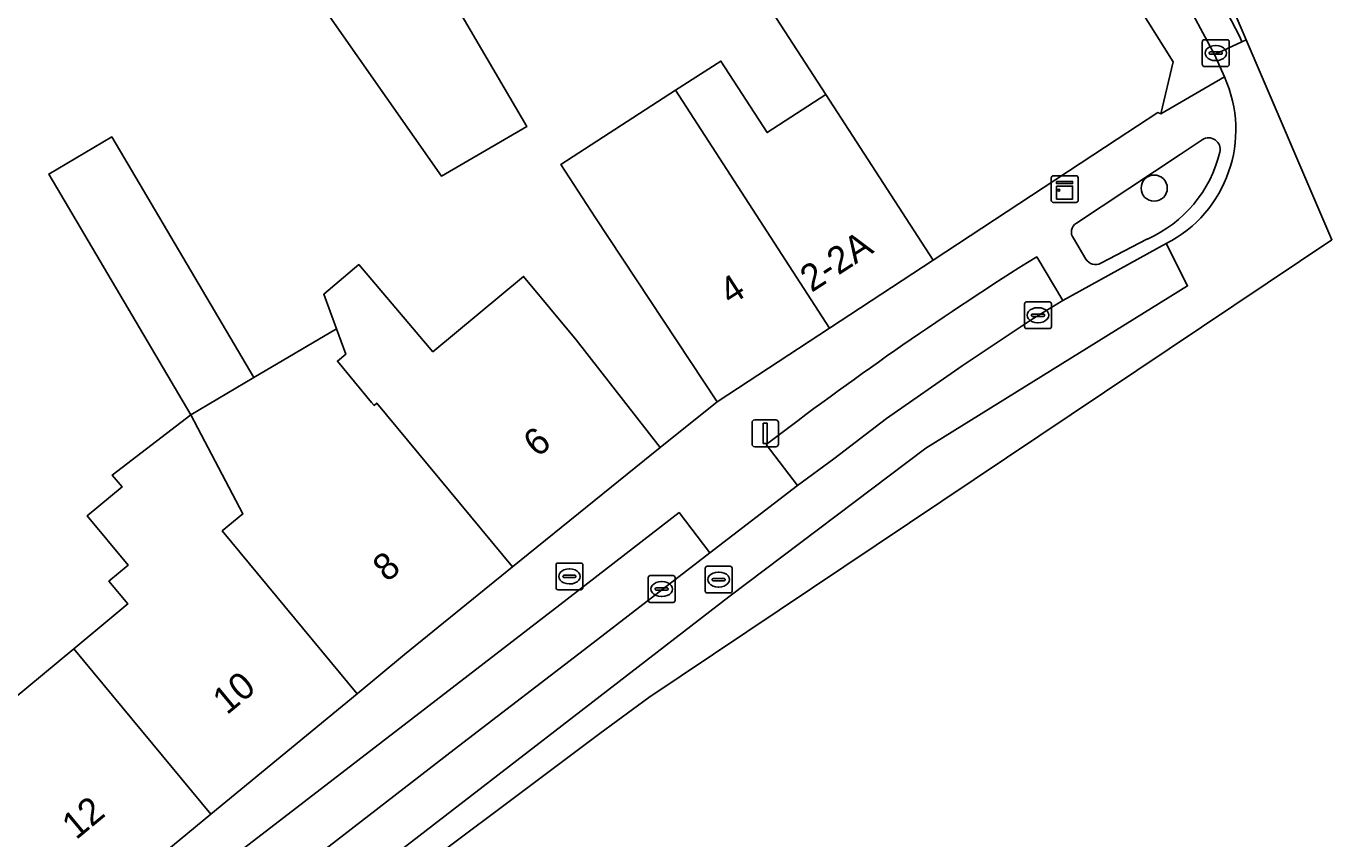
# Model space of a CAD drawing. Extents: x 159371 to 159986, y 382987 to 383597.
# Drawn here: x 159937.11 to 159985.83, y 383267.38 to 383297.7 of the extents above; entities that cross this region are included whole.
import ezdxf

# ---------------------------------------------------------------- set-up
doc = ezdxf.new("R2010")
doc.units = 0
for name, color, linetype in [('IMGEO_Boom', 7, 'Continuous'), ('IMGEO_Brandkraan', 7, 'Continuous'), ('IMGEO_Erf', 7, 'Continuous'), ('IMGEO_Groenvoorziening', 7, 'Continuous'), ('IMGEO_Kast', 7, 'Continuous'), ('IMGEO_Kolk', 7, 'Continuous'), ('IMGEO_Lichtmast', 7, 'Continuous'), ('IMGEO_Pand', 7, 'Continuous'), ('IMGEO_Pand_nummerreeks', 7, 'Continuous'), ('IMGEO_Parkeervlak_open', 7, 'Continuous'), ('IMGEO_Rijbaan_lokaal_gesloten', 7, 'Continuous'), ('IMGEO_Rijbaan_lokaal_open', 7, 'Continuous'), ('IMGEO_Rioolput', 7, 'Continuous'), ('IMGEO_Voetpad_open', 7, 'Continuous')]:
    doc.layers.add(name, color=color, linetype=linetype)

msp = doc.modelspace()

# ---------------------------------------------------------------- linework, layer by layer
at = {"layer": 'IMGEO_Boom'}
msp.add_circle((159979.2, 383291.659), 0.489, dxfattribs=at)
at = {"layer": 'IMGEO_Brandkraan'}
for p, q in [((159956.881, 383276.743), (159956.881, 383277.595)), ((159956.956, 383277.669), (159957.808, 383277.669)), ((159957.882, 383277.595), (159957.882, 383276.743)), ((159957.14, 383277.163), (159957.14, 383277.175)), ((159957.578, 383277.126), (159957.18, 383277.126)), ((159957.183, 383277.212), (159957.581, 383277.212)), ((159957.369, 383277.449), (159957.394, 383277.449)), ((159957.624, 383277.175), (159957.624, 383277.163)), ((159957.808, 383276.669), (159956.956, 383276.669)), ((159957.392, 383276.889), (159957.367, 383276.889))]:
    msp.add_line(p, q, dxfattribs=at)
for points in [[(159956.881, 383276.743), (159956.881, 383277.595)], [(159956.956, 383277.669), (159957.808, 383277.669)], [(159957.882, 383277.595), (159957.882, 383276.743)], [(159957.808, 383276.669), (159956.956, 383276.669)]]:
    msp.add_lwpolyline(points, dxfattribs=at)
for centre, radius, start, end in [((159956.958, 383277.593), 0.0765, 91.552, 178.448), ((159956.958, 383277.593), 0.0765, 91.552, 178.448), ((159957.806, 383277.593), 0.0765, 1.552, 88.448), ((159957.806, 383277.593), 0.0765, 1.552, 88.448), ((159957.18, 383277.172), 0.0403, 85.8775, 175.7526), ((159957.177, 383277.162), 0.0366, 178.938, 274.7102), ((159957.581, 383277.169), 0.043, 264.8664, 352.4533), ((159957.585, 383277.174), 0.0386, 1.7309, 96.639), ((159956.958, 383276.745), 0.0765, 181.552, 268.448), ((159956.958, 383276.745), 0.0765, 181.552, 268.448), ((159957.806, 383276.745), 0.0765, 271.552, 358.448), ((159957.806, 383276.745), 0.0765, 271.552, 358.448)]:
    msp.add_arc(centre, radius, start, end, dxfattribs=at)
for centre, major_axis, ratio, start_param, end_param in [((159957.368, 383277.169), (-0.387, 0.002), 0.722429, 4.712389, 7.853982), ((159957.393, 383277.169), (-0.39, 0.002), 0.717154, 1.570796, 4.712389)]:
    msp.add_ellipse(centre, major_axis=major_axis, ratio=ratio, start_param=start_param, end_param=end_param, dxfattribs=at)
at = {"layer": 'IMGEO_Erf'}
for points in [[(159934.071, 383312.263), (159942.713, 383316.486), (159947.811, 383307.547), (159949.364, 383304.957), (159949.605, 383304.544), (159949.745, 383304.614), (159948.027, 383308.209), (159950.905, 383309.585), (159952.605, 383306.029), (159954.438, 383306.935), (159956.105, 383303.788), (159951.562, 383301.19), (159955.785, 383293.954), (159952.607, 383292.1), (159946.404, 383300.967), (159942.065, 383298.484), (159936.196, 383308.615)], [(159933.181, 383269.745), (159938.884, 383274.471), (159940.9, 383276.142), (159940.196, 383276.991), (159940.913, 383277.585), (159939.385, 383279.429), (159940.69, 383280.51), (159940.323, 383280.953), (159943.258, 383283.202), (159937.953, 383292.182), (159940.304, 383293.571), (159945.609, 383284.591), (159948.685, 383286.409), (159948.216, 383287.697), (159949.517, 383288.805), (159952.284, 383285.555), (159955.67, 383288.361), (159957.628, 383285.998), (159960.765, 383281.98), (159962.889, 383283.683), (159958.352, 383290.552), (159957.064, 383292.541), (159961.344, 383295.309), (159963.033, 383296.402), (159964.76, 383293.732), (159966.951, 383295.149), (159964.186, 383299.423)]]:
    msp.add_lwpolyline(points, dxfattribs=at)
at = {"layer": 'IMGEO_Groenvoorziening'}
for points in [[(159980.994, 383293.463), (159980.167, 383292.915)], [(159980.167, 383292.915), (159976.297, 383290.349)], [(159976.188, 383289.787), (159976.654, 383289.012)], [(159977.209, 383288.86), (159978.948, 383289.76)]]:
    msp.add_lwpolyline(points, dxfattribs=at)
for centre, radius, start, end in [((159981.233, 383293.107), 0.428, 345.7933, 123.8472), ((159977.012, 383294.117), 4.768, 293.953, 346.4706), ((159976.494, 383290.019), 0.384, 120.8488, 217.1987), ((159977.004, 383289.2), 0.397, 208.2697, 301.0978)]:
    msp.add_arc(centre, radius, start, end, dxfattribs=at)
at = {"layer": 'IMGEO_Kast'}
for p, q in [((159975.436, 383292.121), (159976.277, 383292.121)), ((159976.277, 383292.121), (159975.436, 383292.121)), ((159975.361, 383291.196), (159975.361, 383292.037)), ((159975.361, 383292.037), (159975.361, 383291.196)), ((159976.361, 383292.046), (159976.361, 383291.205)), ((159976.361, 383291.205), (159976.361, 383292.046)), ((159976.286, 383291.121), (159975.445, 383291.121)), ((159975.445, 383291.121), (159976.286, 383291.121))]:
    msp.add_line(p, q, dxfattribs=at)
for points in [[(159975.556, 383291.911), (159976.156, 383291.911), (159976.156, 383291.826), (159975.556, 383291.826), (159975.556, 383291.911)], [(159975.556, 383291.736), (159976.156, 383291.736), (159976.156, 383291.247), (159975.556, 383291.247), (159975.556, 383291.736)]]:
    msp.add_lwpolyline(points, dxfattribs=at)
msp.add_circle((159975.64, 383291.585), 0.0377, dxfattribs=at)
for centre, start, end in [((159975.439, 383292.043), 92.4484, 184.2845), ((159975.439, 383292.043), 92.4484, 184.2845), ((159976.283, 383292.043), 2.4484, 94.2845), ((159976.283, 383292.043), 2.4484, 94.2845), ((159975.439, 383291.199), 182.4484, 274.2845), ((159975.439, 383291.199), 182.4484, 274.2845), ((159976.283, 383291.199), 272.4484, 4.2845), ((159976.283, 383291.199), 272.4484, 4.2845)]:
    msp.add_arc(centre, 0.0779, start, end, dxfattribs=at)
at = {"layer": 'IMGEO_Kolk'}
for p, q in [((159980.996, 383296.27), (159980.996, 383297.122)), ((159981.071, 383297.196), (159981.923, 383297.196)), ((159981.997, 383297.122), (159981.997, 383296.27)), ((159981.255, 383296.69), (159981.255, 383296.702)), ((159981.693, 383296.653), (159981.295, 383296.653)), ((159981.298, 383296.739), (159981.696, 383296.739)), ((159981.484, 383296.976), (159981.509, 383296.976)), ((159981.739, 383296.702), (159981.739, 383296.69)), ((159981.923, 383296.196), (159981.071, 383296.196)), ((159981.507, 383296.416), (159981.482, 383296.416)), ((159974.363, 383286.49), (159974.363, 383287.342)), ((159974.438, 383287.416), (159975.29, 383287.416)), ((159975.364, 383287.342), (159975.364, 383286.49)), ((159974.622, 383286.91), (159974.622, 383286.922)), ((159975.06, 383286.873), (159974.662, 383286.873)), ((159974.665, 383286.959), (159975.063, 383286.959)), ((159974.851, 383287.196), (159974.876, 383287.196)), ((159975.106, 383286.922), (159975.106, 383286.91)), ((159975.29, 383286.416), (159974.438, 383286.416)), ((159974.874, 383286.636), (159974.849, 383286.636)), ((159960.323, 383276.272), (159960.323, 383277.124)), ((159960.398, 383277.198), (159961.25, 383277.198)), ((159961.324, 383277.124), (159961.324, 383276.272)), ((159960.582, 383276.692), (159960.582, 383276.704)), ((159961.02, 383276.655), (159960.622, 383276.655)), ((159960.625, 383276.741), (159961.023, 383276.741)), ((159960.811, 383276.978), (159960.836, 383276.978)), ((159961.066, 383276.704), (159961.066, 383276.692)), ((159961.25, 383276.198), (159960.398, 383276.198)), ((159960.834, 383276.418), (159960.809, 383276.418))]:
    msp.add_line(p, q, dxfattribs=at)
for points in [[(159980.996, 383296.27), (159980.996, 383297.122)], [(159981.071, 383297.196), (159981.923, 383297.196)], [(159981.997, 383297.122), (159981.997, 383296.27)], [(159981.923, 383296.196), (159981.071, 383296.196)], [(159974.363, 383286.49), (159974.363, 383287.342)], [(159974.438, 383287.416), (159975.29, 383287.416)], [(159975.364, 383287.342), (159975.364, 383286.49)], [(159975.29, 383286.416), (159974.438, 383286.416)], [(159960.323, 383276.272), (159960.323, 383277.124)], [(159960.398, 383277.198), (159961.25, 383277.198)], [(159961.324, 383277.124), (159961.324, 383276.272)], [(159961.25, 383276.198), (159960.398, 383276.198)]]:
    msp.add_lwpolyline(points, dxfattribs=at)
for centre, radius, start, end in [((159981.073, 383297.12), 0.0765, 91.552, 178.448), ((159981.073, 383297.12), 0.0765, 91.552, 178.448), ((159981.921, 383297.12), 0.0765, 1.552, 88.448), ((159981.921, 383297.12), 0.0765, 1.552, 88.448), ((159981.295, 383296.699), 0.0403, 85.8775, 175.7526), ((159981.292, 383296.689), 0.0366, 178.938, 274.7102), ((159981.696, 383296.696), 0.043, 264.8664, 352.4533), ((159981.7, 383296.701), 0.0386, 1.7309, 96.639), ((159981.073, 383296.272), 0.0765, 181.552, 268.448), ((159981.073, 383296.272), 0.0765, 181.552, 268.448), ((159981.921, 383296.272), 0.0765, 271.552, 358.448), ((159981.921, 383296.272), 0.0765, 271.552, 358.448), ((159974.44, 383287.34), 0.0765, 91.552, 178.448), ((159974.44, 383287.34), 0.0765, 91.552, 178.448), ((159975.288, 383287.34), 0.0765, 1.552, 88.448), ((159975.288, 383287.34), 0.0765, 1.552, 88.448), ((159974.662, 383286.919), 0.0403, 85.8775, 175.7526), ((159974.659, 383286.909), 0.0366, 178.938, 274.7102), ((159975.063, 383286.916), 0.043, 264.8664, 352.4533), ((159975.067, 383286.921), 0.0386, 1.7309, 96.639), ((159974.44, 383286.492), 0.0765, 181.552, 268.448), ((159974.44, 383286.492), 0.0765, 181.552, 268.448), ((159975.288, 383286.492), 0.0765, 271.552, 358.448), ((159975.288, 383286.492), 0.0765, 271.552, 358.448), ((159960.4, 383277.122), 0.0765, 91.552, 178.448), ((159960.4, 383277.122), 0.0765, 91.552, 178.448), ((159961.248, 383277.122), 0.0765, 1.552, 88.448), ((159961.248, 383277.122), 0.0765, 1.552, 88.448), ((159960.622, 383276.701), 0.0403, 85.8775, 175.7526), ((159960.619, 383276.691), 0.0366, 178.938, 274.7102), ((159961.023, 383276.698), 0.043, 264.8664, 352.4533), ((159961.027, 383276.703), 0.0386, 1.7309, 96.639), ((159960.4, 383276.274), 0.0765, 181.552, 268.448), ((159960.4, 383276.274), 0.0765, 181.552, 268.448), ((159961.248, 383276.274), 0.0765, 271.552, 358.448), ((159961.248, 383276.274), 0.0765, 271.552, 358.448)]:
    msp.add_arc(centre, radius, start, end, dxfattribs=at)
for centre, major_axis, ratio, start_param, end_param in [((159981.483, 383296.696), (-0.387, 0.002), 0.722429, 4.712389, 7.853982), ((159981.508, 383296.696), (-0.39, 0.002), 0.717154, 1.570796, 4.712389), ((159974.85, 383286.916), (-0.387, 0.002), 0.722429, 4.712389, 7.853982), ((159974.875, 383286.916), (-0.39, 0.002), 0.717154, 1.570796, 4.712389), ((159960.81, 383276.698), (-0.387, 0.002), 0.722429, 4.712389, 7.853982), ((159960.835, 383276.698), (-0.39, 0.002), 0.717154, 1.570796, 4.712389)]:
    msp.add_ellipse(centre, major_axis=major_axis, ratio=ratio, start_param=start_param, end_param=end_param, dxfattribs=at)
at = {"layer": 'IMGEO_Lichtmast'}
for p, q in [((159964.193, 383282.107), (159964.193, 383282.907)), ((159964.193, 383282.907), (159964.193, 383282.107)), ((159964.293, 383283.007), (159965.083, 383283.007)), ((159965.083, 383283.007), (159964.293, 383283.007)), ((159965.183, 383282.907), (159965.183, 383282.107)), ((159965.183, 383282.107), (159965.183, 383282.907)), ((159965.083, 383282.007), (159964.293, 383282.007)), ((159964.293, 383282.007), (159965.083, 383282.007))]:
    msp.add_line(p, q, dxfattribs=at)
msp.add_lwpolyline([(159964.613, 383282.882), (159964.763, 383282.882), (159964.763, 383282.132), (159964.613, 383282.132), (159964.613, 383282.882)], dxfattribs=at)
for centre, start, end in [((159964.293, 383282.907), 90, 180), ((159964.293, 383282.907), 90, 180), ((159965.083, 383282.907), 0, 90), ((159965.083, 383282.907), 360, 90), ((159964.293, 383282.107), 180, 270), ((159964.293, 383282.107), 180, 270), ((159965.083, 383282.107), 270, 0), ((159965.083, 383282.107), 270, 0)]:
    msp.add_arc(centre, 0.1, start, end, dxfattribs=at)
at = {"layer": 'IMGEO_Pand'}
for points in [[(159951.562, 383301.19), (159949.605, 383304.544), (159949.364, 383304.957), (159947.811, 383307.547), (159944.953, 383305.96), (159943.837, 383305.341), (159944.439, 383304.314), (159946.404, 383300.967), (159952.607, 383292.1), (159955.785, 383293.954)], [(159977.007, 383300.995), (159974.015, 383305.934), (159973.493, 383305.565), (159967.948, 383301.873), (159964.186, 383299.423), (159966.951, 383295.149), (159970.948, 383288.972), (159977.824, 383293.484), (159979.338, 383294.477), (159979.443, 383294.433), (159979.906, 383296.377)], [(159966.951, 383295.149), (159964.76, 383293.732), (159963.033, 383296.402), (159961.344, 383295.309), (159967.084, 383286.436), (159970.948, 383288.972)], [(159961.344, 383295.309), (159957.064, 383292.541), (159958.352, 383290.552), (159962.889, 383283.683), (159967.084, 383286.436)], [(159943.258, 383283.202), (159945.609, 383284.591), (159940.304, 383293.571), (159937.953, 383292.182)], [(159957.628, 383285.998), (159955.67, 383288.361), (159952.284, 383285.555), (159949.517, 383288.805), (159948.216, 383287.697), (159948.685, 383286.409), (159949.032, 383285.458), (159948.723, 383285.202), (159949.999, 383283.661), (159950.089, 383283.553), (159950.192, 383283.638), (159955.259, 383277.521), (159960.765, 383281.98)], [(159950.192, 383283.638), (159950.089, 383283.553), (159949.999, 383283.661), (159948.723, 383285.202), (159949.032, 383285.458), (159948.685, 383286.409), (159945.609, 383284.591), (159943.258, 383283.202), (159945.199, 383279.501), (159944.428, 383278.864), (159949.457, 383272.794), (159951.228, 383274.256), (159955.259, 383277.521)], [(159944.428, 383278.864), (159945.199, 383279.501), (159943.258, 383283.202), (159940.323, 383280.953), (159940.69, 383280.51), (159939.385, 383279.429), (159940.913, 383277.585), (159940.196, 383276.991), (159940.9, 383276.142), (159938.884, 383274.471), (159944.004, 383268.292), (159949.457, 383272.794)], [(159938.884, 383274.471), (159933.181, 383269.745), (159935.149, 383267.369), (159938.069, 383263.392), (159944.004, 383268.292)]]:
    msp.add_lwpolyline(points, close=True, dxfattribs=at)
at = {"layer": 'IMGEO_Parkeervlak_open'}
for points in [[(159975.79, 383287.47), (159974.818, 383289.093), (159974.467, 383288.882)], [(159964.726, 383282.091), (159965.889, 383280.562), (159967.243, 383281.552), (159969.214, 383283.058), (159972.039, 383285.028), (159974.644, 383286.763), (159975.79, 383287.47)], [(159962.619, 383278.043), (159961.472, 383279.55), (159957.026, 383276.108), (159952.409, 383272.555), (159946.562, 383268.05), (159942.629, 383265.026)], [(159943.207, 383263.055), (159948.03, 383266.805), (159953.082, 383270.715), (159958.262, 383274.696), (159962.619, 383278.043)]]:
    msp.add_lwpolyline(points, dxfattribs=at)
msp.add_arc((160045.816, 383176.157), 133.408, 122.33176, 127.4333, dxfattribs=at)
at = {"layer": 'IMGEO_Rijbaan_lokaal_gesloten'}
msp.add_lwpolyline([(159955.349, 383356.123), (159945.45, 383379.953), (159944.818, 383381.47), (159943.844, 383381.078), (159943.997, 383380.769), (159949.547, 383367.357), (159955.098, 383353.99), (159959.545, 383343.383), (159965.129, 383329.956), (159966.033, 383327.842), (159967.899, 383323.262), (159968.686, 383321.639), (159971.968, 383315.21), (159980.218, 383298.949), (159981.447, 383296.649), (159982.474, 383297.117), (159982.396, 383297.308), (159979.747, 383302.409), (159974.947, 383311.811), (159970.698, 383320.214), (159967.997, 383325.865)], close=True, dxfattribs=at)
msp.add_lwpolyline([(159949.02, 383265.371), (159949.631, 383265.838), (159963.334, 383276.404), (159970.676, 383281.955), (159980.447, 383288.011), (159979.648, 383289.586), (159975.79, 383287.47), (159974.644, 383286.763), (159972.039, 383285.028), (159969.214, 383283.058), (159967.243, 383281.552), (159965.889, 383280.562), (159962.619, 383278.043), (159958.262, 383274.696), (159953.082, 383270.715), (159948.03, 383266.805), (159943.207, 383263.055), (159942.046, 383262.195), (159939.889, 383260.569), (159938.953, 383259.858), (159928.303, 383251.721)], dxfattribs=at)
at = {"layer": 'IMGEO_Rijbaan_lokaal_open'}
msp.add_lwpolyline([(159982.637, 383297.191), (159969, 383329.052), (159952.719, 383367.092), (159946.492, 383382.144), (159944.818, 383381.47), (159945.45, 383379.953), (159955.349, 383356.123), (159967.997, 383325.865), (159970.698, 383320.214), (159974.947, 383311.811), (159979.747, 383302.409), (159982.396, 383297.308), (159982.474, 383297.117)], close=True, dxfattribs=at)
for points in [[(159960.338, 383272.649), (159985.83, 383289.731), (159982.637, 383297.191), (159982.474, 383297.117), (159981.447, 383296.649), (159981.823, 383295.807)], [(159979.648, 383289.586), (159980.447, 383288.011), (159970.676, 383281.955), (159963.334, 383276.404), (159949.631, 383265.838), (159949.02, 383265.371), (159949.617, 383264.636), (159958.513, 383271.311), (159960.338, 383272.649)]]:
    msp.add_lwpolyline(points, dxfattribs=at)
msp.add_arc((159977.46, 383293.842), 4.785, 297.2078, 24.2507, dxfattribs=at)
at = {"layer": 'IMGEO_Rioolput'}
for p, q in [((159962.523, 383277.551), (159963.375, 383277.551)), ((159962.448, 383276.625), (159962.448, 383277.477)), ((159962.707, 383277.045), (159962.707, 383277.057)), ((159962.75, 383277.094), (159963.148, 383277.094)), ((159962.936, 383277.331), (159962.961, 383277.331)), ((159963.191, 383277.057), (159963.191, 383277.045)), ((159963.449, 383277.477), (159963.449, 383276.625)), ((159963.375, 383276.551), (159962.523, 383276.551)), ((159963.145, 383277.008), (159962.747, 383277.008)), ((159962.959, 383276.771), (159962.934, 383276.771))]:
    msp.add_line(p, q, dxfattribs=at)
for points in [[(159962.523, 383277.551), (159963.375, 383277.551)], [(159962.448, 383276.625), (159962.448, 383277.477)], [(159963.449, 383277.477), (159963.449, 383276.625)], [(159963.375, 383276.551), (159962.523, 383276.551)]]:
    msp.add_lwpolyline(points, dxfattribs=at)
for centre, radius, start, end in [((159962.525, 383277.475), 0.0765, 91.552, 178.448), ((159962.525, 383277.475), 0.0765, 91.552, 178.448), ((159963.373, 383277.475), 0.0765, 1.552, 88.448), ((159963.373, 383277.475), 0.0765, 1.552, 88.448), ((159962.747, 383277.054), 0.0403, 85.8775, 175.7526), ((159962.744, 383277.044), 0.0366, 178.938, 274.7102), ((159963.148, 383277.051), 0.043, 264.8664, 352.4533), ((159963.152, 383277.056), 0.0386, 1.7309, 96.639), ((159962.525, 383276.627), 0.0765, 181.552, 268.448), ((159962.525, 383276.627), 0.0765, 181.552, 268.448), ((159963.373, 383276.627), 0.0765, 271.552, 358.448), ((159963.373, 383276.627), 0.0765, 271.552, 358.448)]:
    msp.add_arc(centre, radius, start, end, dxfattribs=at)
for centre, major_axis, ratio, start_param, end_param in [((159962.935, 383277.051), (-0.387, 0.002), 0.722429, 4.712389, 7.853982), ((159962.96, 383277.051), (-0.39, 0.002), 0.717154, 1.570796, 4.712389)]:
    msp.add_ellipse(centre, major_axis=major_axis, ratio=ratio, start_param=start_param, end_param=end_param, dxfattribs=at)
at = {"layer": 'IMGEO_Voetpad_open'}
for points in [[(159961.392, 383334.091), (159964.191, 383327.419), (159964.378, 383326.953), (159965.489, 383324.198), (159965.863, 383323.269), (159969.264, 383314.829), (159969.612, 383313.966), (159972.441, 383307.245), (159973.493, 383305.565), (159974.015, 383305.934), (159977.007, 383300.995), (159979.906, 383296.377), (159979.443, 383294.433), (159981.823, 383295.807), (159981.447, 383296.649), (159980.218, 383298.949), (159971.968, 383315.21), (159968.686, 383321.639), (159967.899, 383323.262), (159966.936, 383322.87), (159965.07, 383327.45), (159966.033, 383327.842), (159965.129, 383329.956), (159959.545, 383343.383)], [(159981.823, 383295.807), (159979.443, 383294.433), (159979.338, 383294.477), (159977.824, 383293.484), (159970.948, 383288.972), (159967.084, 383286.436), (159962.889, 383283.683), (159960.765, 383281.98), (159955.259, 383277.521), (159951.228, 383274.256), (159949.457, 383272.794), (159944.004, 383268.292), (159938.069, 383263.392), (159936.262, 383261.889)], [(159976.297, 383290.349), (159980.167, 383292.915), (159980.994, 383293.463)], [(159976.654, 383289.012), (159976.188, 383289.787)], [(159978.948, 383289.76), (159977.209, 383288.86)], [(159974.467, 383288.882), (159974.818, 383289.093), (159975.79, 383287.47), (159979.648, 383289.586)], [(159938.953, 383259.858), (159939.889, 383260.569), (159942.046, 383262.195), (159940.88, 383263.68), (159942.629, 383265.026), (159946.562, 383268.05), (159952.409, 383272.555), (159957.026, 383276.108), (159961.472, 383279.55), (159962.619, 383278.043), (159965.889, 383280.562), (159964.726, 383282.091)]]:
    msp.add_lwpolyline(points, dxfattribs=at)
for centre, radius, start, end in [((159977.46, 383293.842), 4.785, 297.2078, 24.2507), ((159981.233, 383293.107), 0.428, 345.7933, 123.8472), ((159977.012, 383294.117), 4.768, 293.953, 346.4706), ((159976.494, 383290.019), 0.384, 120.8488, 217.1987), ((160045.816, 383176.157), 133.408, 122.33176, 127.4333), ((159977.004, 383289.2), 0.397, 208.2697, 301.0978)]:
    msp.add_arc(centre, radius, start, end, dxfattribs=at)

# ---------------------------------------------------------------- texts
at = {"layer": 'IMGEO_Pand_nummerreeks'}
for s, rotation, p in [('2-2A', 32.9737, (159966.415, 383287.746)), ('4', 32.7675, (159963.395, 383287.264)), ('6', 39.6487, (159956.189, 383281.582)), ('8', 39.6487, (159950.572, 383276.928)), ('10', 39.6487, (159944.598, 383271.977)), ('12', 39.6487, (159938.973, 383267.316))]:
    msp.add_text(s, height=1, rotation=rotation, dxfattribs=at).set_placement(p)

doc.saveas('drawing.dxf')
